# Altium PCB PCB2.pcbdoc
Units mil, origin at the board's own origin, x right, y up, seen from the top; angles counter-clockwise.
Board outline 3201.08 x 2165 mil, 2 copper layers (Top Layer, Bottom Layer); 34 components, 17 nets, 90 pads, 14 vias.
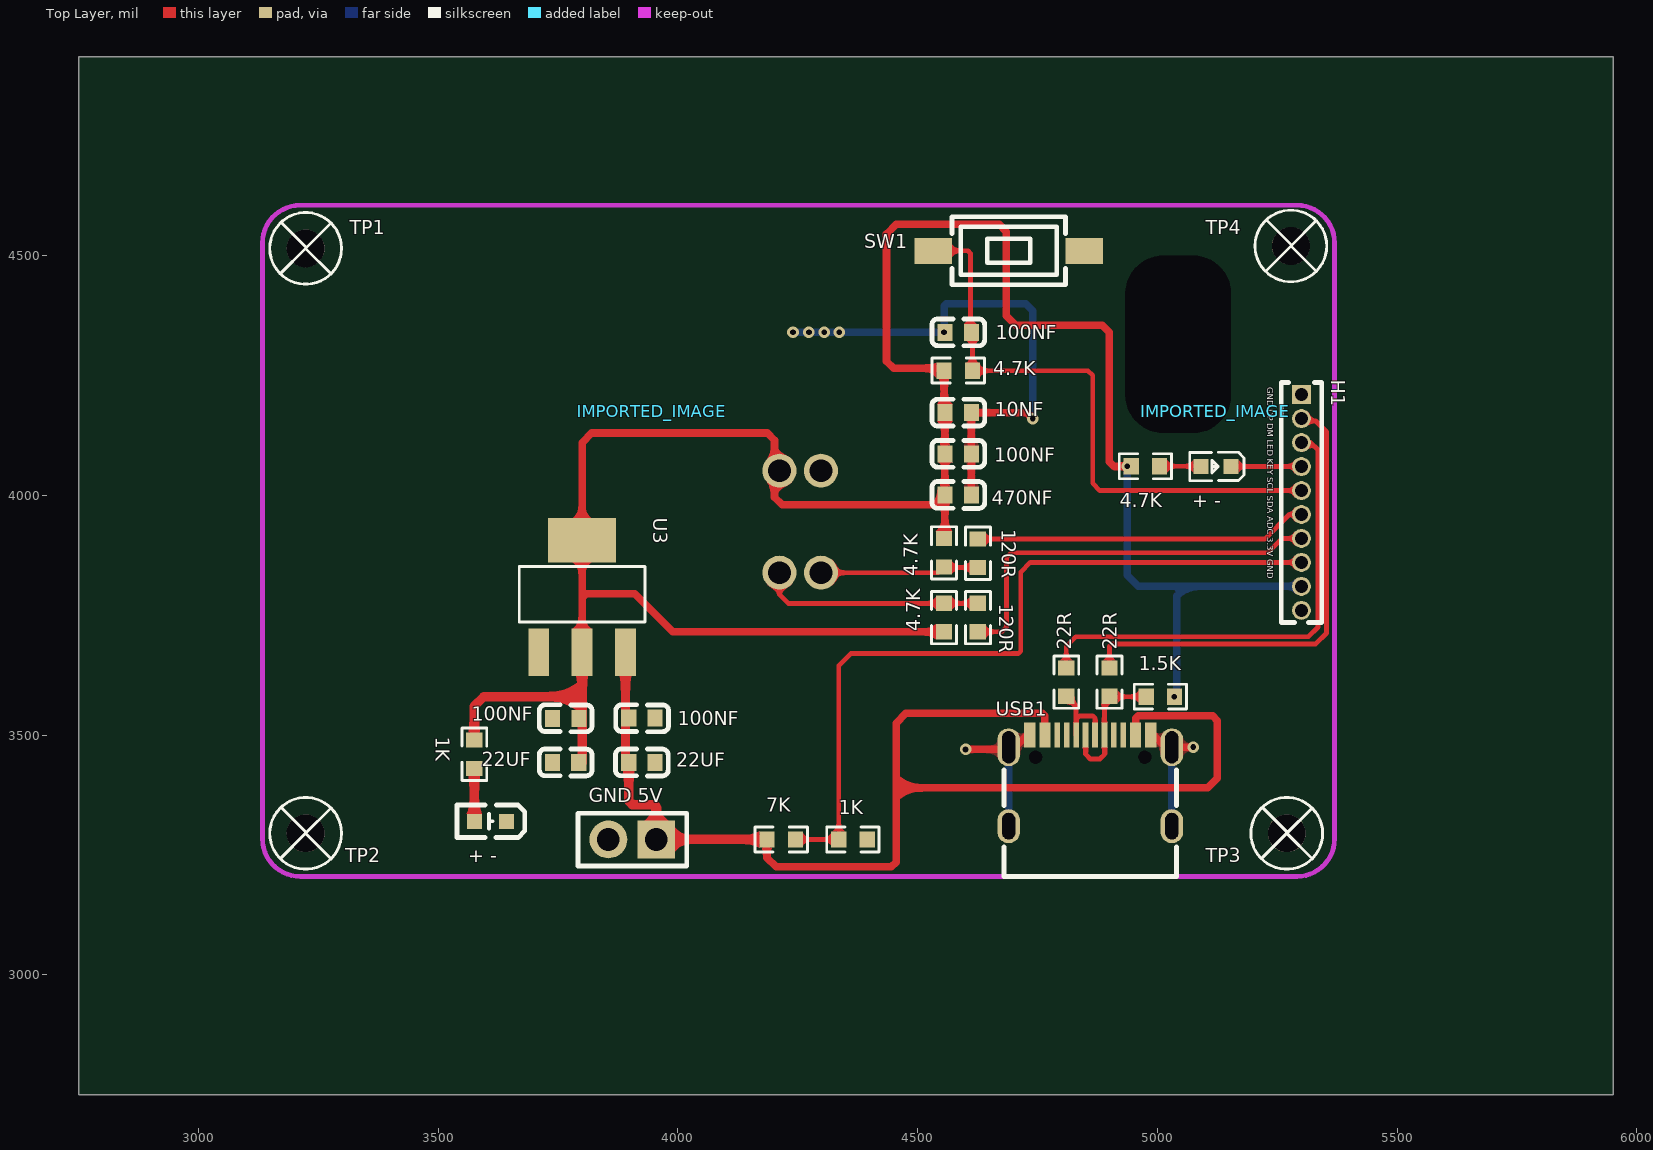
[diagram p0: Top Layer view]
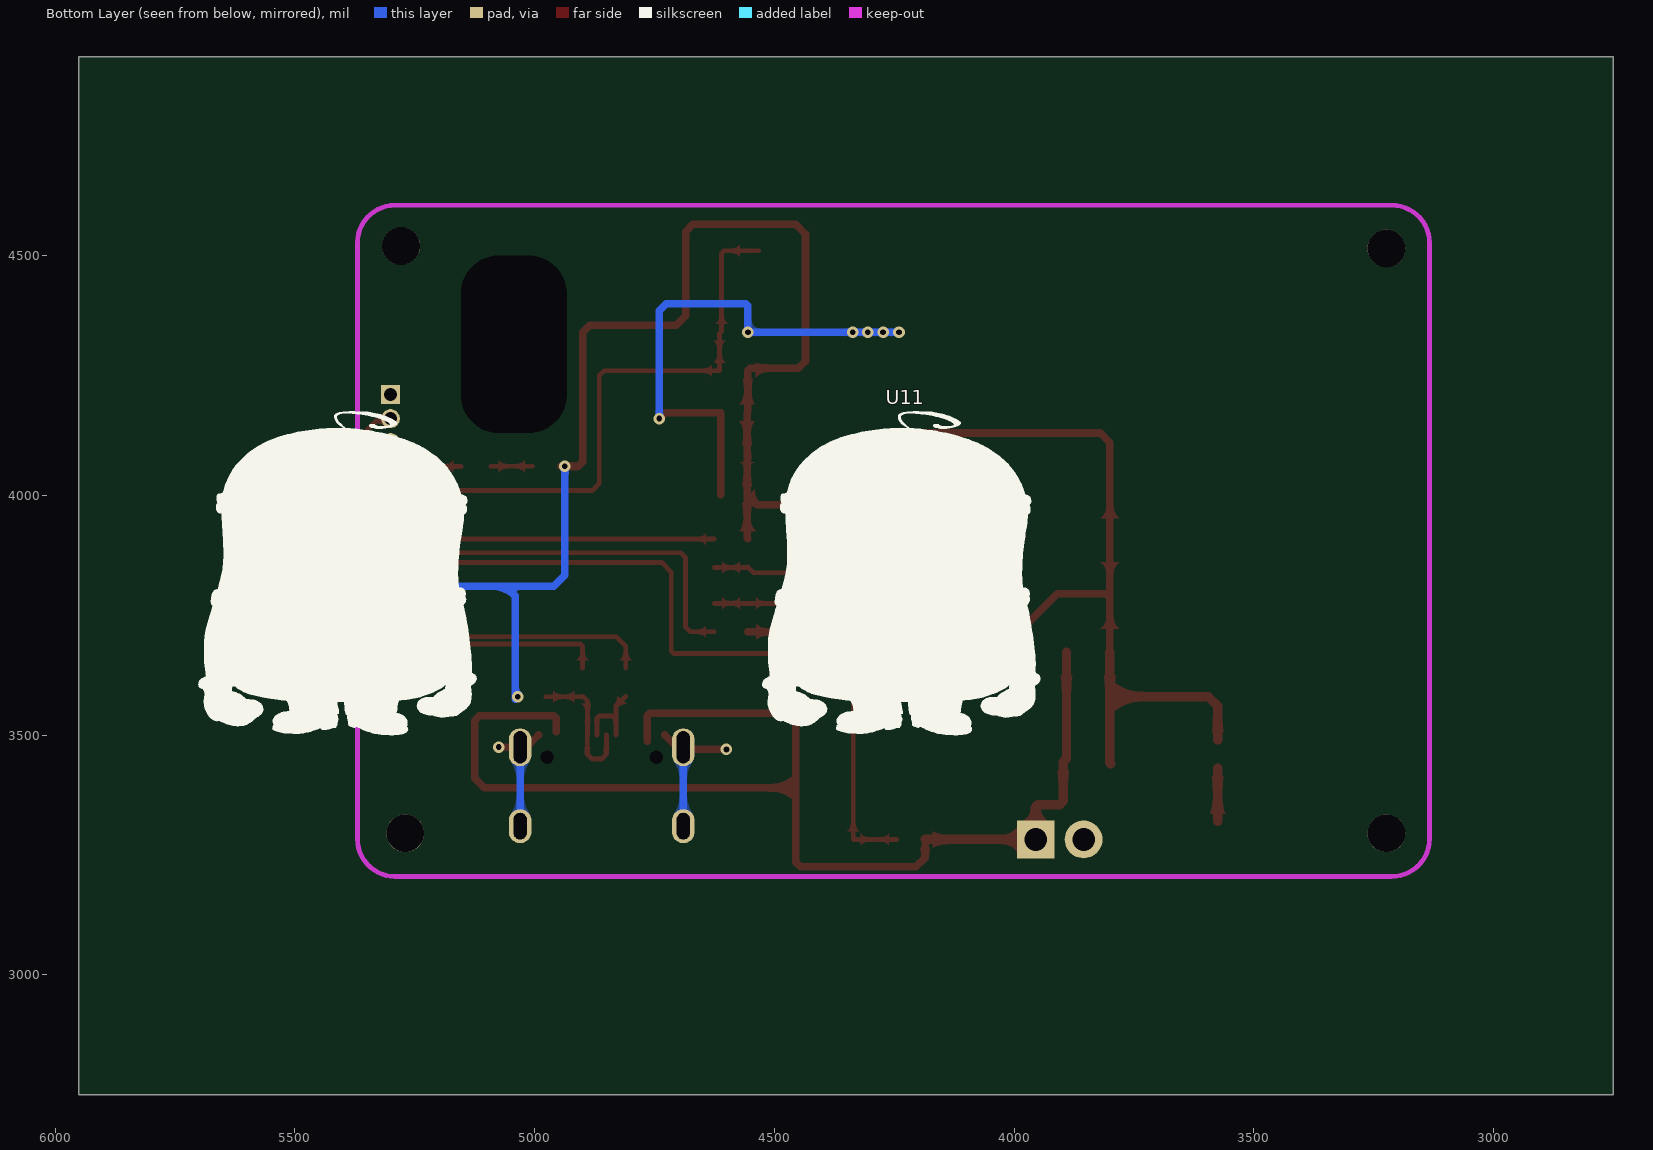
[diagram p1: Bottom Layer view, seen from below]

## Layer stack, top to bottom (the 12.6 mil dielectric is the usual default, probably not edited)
Top Layer: signal copper (thickness not stored)
Dielectric: dielectric 12.6, FR-4, Dk 4.8
Bottom Layer: signal copper (thickness not stored)

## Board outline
5951.08,2750 2750,2750 2750,4915 5951.08,4915
cut-out: 5012.18,4500 5074.7,4500 cw(c5074.7,4421.26) 5153.44,4421.26 5153.44,4208.74 cw(c5074.7,4208.74) 5074.7,4130 5012.18,4130 cw(c5012.18,4208.74) 4933.44,4208.74 4933.44,4421.26 cw(c5012.18,4421.26)

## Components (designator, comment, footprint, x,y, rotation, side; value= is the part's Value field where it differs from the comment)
1.5K "Res_0603" R0603 5006.28,3580 r180 top
1K "ERJ3GEYJ102V" R0603 3575.25,3460 r270 top
1K "Res_0603" R0603 4365,3282.24 r180 top
4.7K "Res_0603" R0603 4555,3745 r90 top
4.7K "Res_0603" R0603 4555,3880 r270 top
4.7K "Res_0603" R0603 4584.66,4260 r0 top
4.7K "Res_0603" R0603 4975,4060.56 r0 top
7K "Res_0603" R0603 4215.34,3282.24 r180 top
10NF "CAP_0603" C0603 4584.53,4172.47 r180 top
22R "Res_0603" R0603 4900,3610.34 r90 top
22R "Res_0603" R0603 4810,3610.34 r90 top
22UF "GRM186R60J226ME15D" C0603 3925,3442.73 r0 top
22UF "GRM186R60J226ME15D" C0603 3765.61,3442.94 r180 top
100NF "CAP_0603" C0603 4584.53,4086.66 r180 top
100NF "CAP_0603" C0603 4584.53,4340 r180 top
100NF "HMK107B7104KA-T" C0603 3925,3535.21 r180 top
100NF "HMK107B7104KA-T" C0603 3766.22,3535 r0 top
120R "Res_0603" R0603 4625.54,3745 r270 top
120R "Res_0603" R0603 4625.54,3879.1 r270 top
470NF "CAP_0603" C0603 4584.53,4000.86 r180 top
"+ -" "LED_0603-R" LED_0603 5120.26,4060 r180 top
"+ -" "SZYY0603B" LED0603-R-RD_BLUE 3609,3320 r180 top
"GND 5V" "HDR-F_2.54_1x2P" HDR-TH_2P-P2.54-V-F 3905,3282.24 r180 top
H1 "KH-1.27PH180-1X10P-L7.2" HDR-TH_10P-P1.27-V-M 5300.5,3985 r270 top
IMPORTED_IMAGE "IMPORTED_IMAGE" IMPORTED_IMAGE 3945,4175.01 r0 top
IMPORTED_IMAGE "IMPORTED_IMAGE" IMPORTED_IMAGE 5121.08,4175.01 r0 top
SW1 "TSA363G25-250B" SW-SMD_L6.1-W3.6-LS8.0 4690,4510 r0 top
TP1 "M2螺丝" M2螺丝 3223.44,4515 r0 top
TP2 "M2螺丝" M2螺丝 3223.44,3295 r0 top
TP3 "M2螺丝" M2螺丝 5269.83,3295 r0 top
TP4 "M2螺丝" M2螺丝 5278.44,4520 r0 top
U3 "AMS1117-3.3_1" SOT-223-3_L6.4-W3.5-P2.30-LS7.0-BR 3800,3789.52 r270 top
U11 "MLX90640ESF-BAB-000-TU" TO-39-4_MELEXIS_MLX90640 4255,3945 r0 bottom
USB1 "kh-type-c-16p" usb-c-smd_kh-type-c-16p 4860,3405 r0 top

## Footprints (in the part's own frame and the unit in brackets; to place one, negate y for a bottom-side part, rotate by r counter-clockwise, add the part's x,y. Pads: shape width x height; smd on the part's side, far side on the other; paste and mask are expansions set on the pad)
C0603 [mm]
  rect 0.8x0.9 smd paste+0 mask+0.051: 1(-0.7,0) 2(0.7,0)
  silkscreen extent -1.41,-0.71 1.39,0.72
HDR-TH_2P-P2.54-V-F [mm]
  rect 2x2 hole 1.2 paste+0 mask+0.051: 1(-1.27,0)
  round 2 hole 1.2 paste+0 mask+0.051: 2(1.27,0)
  silkscreen extent -2.88,-1.39 2.88,1.4
HDR-TH_10P-P1.27-V-M [mm]
  rect 1x1 hole 0.7 mask+0.051: 1(-5.715,0)
  round 1 hole 0.7 mask+0.051: 2(-4.445,0) 3(-3.175,0) 4(-1.905,0) 5(-0.635,0) 6(0.635,0) 7(1.905,0) 8(3.175,0) 9(4.445,0) 10(5.715,0)
  silkscreen extent -6.35,-1.07 6.35,1.07
IMPORTED_IMAGE [mil]
LED0603-R-RD_BLUE [mil]
  rect 31.5x31.5 smd paste+0 mask+2: 1(33.5,0) 2(-33.5,0)
  silkscreen extent -72,-34 70,34
LED_0603 [mil]
  rect 31.5x31.5 smd paste+0 mask+2: 1(-33.5,-0.4) 2(29.5,-0.2)
  silkscreen extent -61,-30 53,30
M2螺丝 [mm]
  round 2 hole 2 mask+0.051: 1(0,0)
  silkscreen extent -1.9,-1.9 1.9,1.9
R0603 [mil]
  rect 31.75x34.02 smd paste-3937.01 mask+2: 1(-29.66,0) 2(29.66,0)
  silkscreen extent -55,-26 55,26
SOT-223-3_L6.4-W3.5-P2.30-LS7.0-BR [mil]
  rect 98.4x43.3 smd paste+0 mask+2: 1(116.9,-90.5) 2(116.9,0) 3(116.9,90.6)
  rect 92.1x141.7 smd paste+0 mask+2: 4(-116.9,0)
  silkscreen extent -62,-131 54,131
SW-SMD_L6.1-W3.6-LS8.0 [mm]
  rect 2x1.38 smd mask+0.051: 1(-4,0) 2(4,0)
  silkscreen extent -3,-1.8 3,1.8
TO-39-4_MELEXIS_MLX90640 [mm]
  round 1.8 hole 1.2 copper offset 0,-0.001 paste+0 mask+0.05: 1(-1.1,2.699) 2(-1.1,-2.701) 3(1.101,-2.701) 4(1.101,2.699)
  silkscreen extent -4.6,-4.6 4.6,5.3
usb-c-smd_kh-type-c-16p [mm]
  oval 1.2x2 hole 0.7 slot 1.7 at 90 deg paste+0 mask+0.051: 1(-4.32,1.765) 2(4.32,1.765)
  oval 1.2x1.8 hole 0.7 slot 1.4 at 90 deg paste+0 mask+0.051: 3(-4.32,-2.415) 4(4.32,-2.415)
  rect 0.3x1.3 smd paste-100 mask+0.051: A1(-3.35,2.415) A4(-2.55,2.415) A5(-1.25,2.415) A6(-0.25,2.415) A7(0.25,2.415) A8(1.25,2.415) A9(2.55,2.415) A12(3.35,2.415) B1(3.05,2.415) B4(2.25,2.415) B5(1.75,2.415) B6(0.75,2.415) B7(-0.75,2.415) B8(-1.75,2.415) B9(-2.25,2.415) B12(-3.05,2.415)
  Multi-Layer board cut-out: -2.54,1.235 -2.575,1.387 -2.672,1.509 -2.812,1.576 -2.968,1.576 -3.108,1.509 -3.205,1.387 -3.24,1.235 -3.24,1.235 -3.205,1.083 -3.108,0.961 -2.968,0.894 -2.812,0.894 -2.672,0.961 -2.575,1.083 -2.54,1.235
  Multi-Layer board cut-out: 3.24,1.235 3.205,1.387 3.108,1.509 2.968,1.576 2.812,1.576 2.672,1.509 2.575,1.387 2.54,1.235 2.54,1.235 2.575,1.083 2.672,0.961 2.812,0.894 2.968,0.894 3.108,0.961 3.205,1.083 3.24,1.235
  silkscreen extent -4.57,-5.08 4.57,0.57

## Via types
v1: diameter 24.02, hole 12.01, Top Layer to Bottom Layer, 14 vias

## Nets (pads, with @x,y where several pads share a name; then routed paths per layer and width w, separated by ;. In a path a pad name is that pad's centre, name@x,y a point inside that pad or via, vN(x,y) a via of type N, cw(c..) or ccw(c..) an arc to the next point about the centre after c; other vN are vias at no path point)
$1N282: 4.7K.2@4555,3774.66 120R.1@4625.54,3774.66 U11.1 | length 467
  Top Layer w10: U11.1 4211.69,3793.31 4230.34,3774.66 4555,3774.66 120R.1@4625.54,3774.66
$1N283: 4.7K.2@4555,3850.34 120R.2@4625.54,3849.44 U11.4 | length 332.4
  Top Layer w10: U11.4 4543.36,3838.7 4555,3850.34 4555.9,3849.44 120R.2@4625.54,3849.44
$1N1069: 4.7K.2@5004.66,4060.56 "+ -.2"@5090.76,4060.2 | length 86.3
  Top Layer w10: 4.7K.2@5004.66,4060.56 5090.41,4060.56 5090.76,4060.2
$1N1386: 1K.2@3575.25,3430.34 "+ -.1"@3575.5,3320 | length 110.4
  Top Layer w19.68: 1K.2@3575.25,3430.34 3575.25,3320.25 3575.5,3320
+3.3V: 1.5K.1 1K.1@3575.25,3489.66 4.7K.1 10NF.2 22UF.1@3793.17,3442.94 100NF.2@3793.78,3535 100NF.2@4556.97,4086.66 470NF.2 H1.9 U3.2 U3.4 U11.2 | length 5276.9
  Top Layer w15.75: U3.2 3800,3786.63 ; 4.7K.1@4555,3715.34 3989.66,3715.34 3910,3795 3808.37,3795 3800,3786.63 ; 4.7K.1@4555,3909.66 4556.97,3911.63 470NF.2 ; 4.7K.1@4945.34,4060.56 4909.44,4060.56 4900,4070 4900,4340 4885,4355 4705,4355 4685,4375 4685,4550 4670,4565 4455,4565 4435,4545 4435,4280 4450,4265 4550,4265 4555,4260 4555,4174.44 10NF.2 100NF.2@4556.97,4086.66 ; 3800,3786.63 U3.4 3800,4110 3820,4130 4186.42,4130 4201.42,4115 4201.42,3995.75 4217.16,3980 4536.11,3980 470NF.2 ; 470NF.2 4556.97,4060 ; 4556.97,4060 4555,4084.7 100NF.2@4556.97,4086.66 ; 4556.97,4060 100NF.2@4556.97,4086.66
  Top Layer w19.68: 1K.1@3575.25,3489.66 3575.25,3560.25 3595,3580 3799.29,3580 3800,3580.71 ; 22UF.1@3798.17,3440 3800,3441.83 3800,3580.71 ; U3.2 3800,3580.71
  Bottom Layer w15.75: v1(4936.91,4060.56) 4936.91,3833.09 4960,3810 5060,3810 ; v1@5040,3575 5040,3790 5060,3810 ; v1(5300.5,3810) 5060,3810
  other v1: 5035.22,3579.72
+5V: 7K.2 22UF.1@3897.44,3442.73 100NF.2@3897.44,3535.21 "GND 5V.1" U3.3 USB1.A4 USB1.A9 USB1.B4 USB1.B9 | length 2652.1
  Top Layer w15.75: 7K.2 4185.68,3244.32 4205,3225 4445,3225 4455,3235 4455,3392.84 ; USB1.A4@4765,3486.9 4765,3540 4760,3545 4475,3545 4455,3525 4455,3392.84 ; USB1.A9@4955,3506.49 4955,3535 4960,3540 5115,3540 5125,3530 5125,3410 5105,3390 4457.85,3390 4455,3392.84
  Top Layer w19.68: U3.3 3890.6,3450.89 22UF.1@3897.44,3444.05 ; 22UF.1@3897.44,3435 3897.44,3362.56 3905,3355 3950,3355 3955,3350 3955,3282.24 7K.2
BAT_ADC: 1K.2@4335.34,3282.24 7K.1 H1.8 | length 1603.9
  Top Layer w10: 7K.1 4335.34,3282.24 4335.34,3644.88 4360.46,3670 4710,3670 4715,3675 4715,3840 4735,3860 H1.8
GND: 1K.1@4394.66,3282.24 10NF.1 22UF.2 100NF.1@3738.66,3535 100NF.1@3952.56,3535.21 100NF.1@4612.09,4086.66 100NF.2@4556.97,4340 470NF.1 "+ -.2"@3642.5,3320 "GND 5V.2" H1.1 H1.10 SW1.2 U3.1 U11.3 USB1.1 USB1.2 USB1.3 USB1.4 USB1.A1 USB1.A12 USB1.B1 USB1.B12 | length 1656.6
  Top Layer w15.75: v1(4600,3470) 4685.43,3470 USB1.1 4702.52,3474.49 USB1.A1 ; 470NF.1 4612.09,4086.66 10NF.1 4727.53,4172.47 v1(4740,4160) ; USB1.A12 5017.48,3474.49 v1(5030.08,3474.49) 5074.49,3474.49 v1(5075,3475)
  Bottom Layer w15.75: v1(4240,4340) v1(4273.18,4340) v1(4305.35,4340) v1(4336.44,4340) v1(4555,4340) 4555,4395 4560,4400 4725,4400 4740,4385 v1(4740,4160) ; USB1.3 USB1.1 ; USB1.4 v1(5030.08,3474.49)
  other v1: 4740,4160 4740,4160
IIC_SCL: 120R.1@4625.54,3908.76 H1.6 | length 696.2
  Top Layer w10: 120R.1@4625.54,3908.76 5223.76,3908.76 5275,3960 H1.6
IIC_SDA: 120R.2@4625.54,3715.34 H1.7 | length 840.5
  Top Layer w10: 120R.2@4625.54,3715.34 4675.34,3715.34 4685,3725 4685,3870 4695,3880 5230,3880 5260,3910 H1.7
KEY_GPIO: 4.7K.2@4614.32,4260 100NF.1@4612.09,4340 H1.5 SW1.1 | length 1247.9
  Top Layer w10: SW1.1 4605,4510 4610,4505 4610,4342.09 4612.09,4340 4614.32,4337.77 4614.32,4260 4855,4260 4865,4250 4865,4025 4880,4010 H1.5
LED_GPIO: "+ -.1"@5153.76,4060.4 H1.4 | length 146.9
  Top Layer w10: 5153.76,4060.4 5300.1,4060.4 H1.4
USB-D+: 1.5K.2 22R.1@4900,3580.68 USB1.A6 USB1.B6 | length 290.4
  Top Layer w10: USB1.A6 4850.16,3459.84 4860,3450 4880,3450 4890,3460 4890,3499.61 USB1.B6 4889.53,3570.21 4900,3580.68 4900.68,3580 1.5K.2
USB-D-: 22R.1@4810,3580.68 USB1.A7 USB1.B7 | length 168.7
  Top Layer w10: 22R.1@4810,3580.68 4830.47,3560.21 4830.47,3532.59 ; USB1.B7 4830.47,3532.59 ; USB1.A7 4870,3500.24 4870,3535 4865,3540 4837.88,3540 4830.47,3532.59
USB_FS_DM: 22R.2@4810,3640 H1.3 | length 997.3
  Top Layer w10: 22R.2@4810,3640 4810,3685 4830,3705 5315,3705 5335,3725 5335,4095 5320,4110 H1.3
USB_FS_DP: 22R.2@4900,3640 H1.2 | length 992.6
  Top Layer w10: 22R.2@4900,3640 4900,3685 4905,3690 5330,3690 5352.86,3712.86 5352.86,4132.14 5330,4155 5305.5,4155 H1.2
"": TP1.1 TP2.1 TP3.1 TP4.1 USB1.A5 USB1.A8 USB1.B5 USB1.B8

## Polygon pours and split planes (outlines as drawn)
GND on Bottom Layer (hatched 45Degree grid 30 track 10, remove dead copper, pour order 0): 3000,3100 5415,3100 5415,4665 3000,4665
GND on Top Layer (hatched 45Degree grid 30 track 10, remove dead copper, pour order 1): 3105,3000 5540,3000 5540,4660 3105,4660

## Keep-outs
Board Outline Layer:
  lines w10 net "": 3133.44,3283.74 ccw(c3212.18,3283.74) 3212.18,3205 5290.92,3205 ccw(c5290.92,3283.74) 5369.66,3283.74 5369.66,4526.26 ccw(c5290.92,4526.26) 5290.92,4605 3212.18,4605 ccw(c3212.18,4526.26) 3133.44,4526.26 3133.44,3283.74

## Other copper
Top Layer:
  region net +3.3V: 4209.29,4099.54 4193.54,4099.54 4193.45,4097.3 4193.2,4094.91 4192.78,4092.41 4192.21,4089.85 4191.49,4087.28 4190.64,4084.74 4189.66,4082.28 4188.56,4079.95 4187.77,4078.5 4186.93,4077.13 4186.04,4075.88 4185.12,4074.74 4238.27,4074.74 4237.55,4075.5 4236.75,4076.25 4235.42,4077.35 4233.43,4078.79 4230.11,4080.89 4220.47,4086.47 4217.62,4088.3 4215.52,4089.81 4214.09,4090.99 4213.21,4091.79 4212.4,4092.62 4211.68,4093.46 4211.03,4094.33 4210.48,4095.21 4210.02,4096.13 4209.83,4096.6 4209.67,4097.07 4209.54,4097.55 4209.43,4098.04 4209.35,4098.53 4209.31,4099.03
  region net +3.3V: 4193.54,4003.06 4209.29,4003.06 4209.31,4003.57 4209.35,4004.07 4209.43,4004.57 4209.54,4005.06 4209.67,4005.54 4209.83,4006.01 4210.02,4006.48 4210.48,4007.39 4211.03,4008.28 4211.68,4009.14 4212.4,4009.99 4213.21,4010.81 4214.55,4012.01 4216.03,4013.18 4218.17,4014.68 4222.26,4017.2 4231.25,4022.41 4233.95,4024.17 4235.42,4025.25 4236.75,4026.35 4237.55,4027.1 4238.27,4027.87 4185.12,4027.87 4186.04,4026.73 4186.93,4025.47 4187.77,4024.11 4188.94,4021.89 4190,4019.51 4190.94,4017.03 4191.74,4014.47 4192.41,4011.9 4192.93,4009.35 4193.3,4006.88 4193.5,4004.53
  region net $1N283: 4346.55,3833.7 4346.55,3843.7 4344.39,3843.77 4343.08,3843.89 4341.87,3844.07 4340.76,3844.31 4339.74,3844.6 4338.79,3844.95 4337.92,3845.34 4337.12,3845.78 4336.38,3846.27 4335.7,3846.81 4335.06,3847.38 4334.47,3848 4333.91,3848.65 4333.12,3849.7 4332.13,3851.22 4329.36,3855.95 4327.86,3858.31 4326.45,3860.26 4325.24,3861.75 4323.86,3863.26 4322.31,3864.77 4321.75,3865.28 4321.75,3812.13 4323.37,3813.64 4324.8,3815.15 4326.06,3816.65 4327.53,3818.61 4329.08,3820.99 4331.89,3825.79 4332.87,3827.34 4333.64,3828.41 4334.18,3829.08 4334.76,3829.72 4335.38,3830.32 4336.04,3830.87 4336.75,3831.38 4337.52,3831.85 4338.35,3832.27 4339.25,3832.64 4340.24,3832.95 4341.3,3833.22 4342.46,3833.43 4343.72,3833.58 4345.8,3833.69
  region net $1N282: 4206.69,3793.31 4216.69,3793.31 4216.74,3794.07 4216.87,3794.83 4217.1,3795.59 4217.4,3796.34 4217.77,3797.09 4218.22,3797.84 4218.73,3798.58 4219.93,3800.05 4221.33,3801.51 4223.72,3803.65 4228.16,3807.11 4235.05,3812.29 4236.49,3813.5 4237.73,3814.69 4238.27,3815.27 4185.12,3815.27 4186.25,3814.1 4187.59,3812.9 4190.76,3810.4 4198.8,3804.35 4201.29,3802.23 4202.77,3800.78 4204.08,3799.32 4204.65,3798.58 4205.16,3797.84 4205.61,3797.09 4205.99,3796.34 4206.29,3795.59 4206.51,3794.83 4206.64,3794.07
  region net IIC_SDA: 4657.55,3710.34 4657.55,3720.34 cw(c4657.55,3739.09) 4642.55,3727.84 4642.55,3702.84 cw(c4657.55,3691.59)
  region net $1N282: 4593.53,3779.66 4593.53,3769.66 cw(c4593.53,3750.91) 4608.53,3762.16 4608.53,3787.16 cw(c4593.53,3798.41)
  region net $1N283: 4593.53,3854.44 4593.53,3844.44 cw(c4593.53,3825.69) 4608.53,3836.94 4608.53,3861.94 cw(c4593.53,3873.19)
  region net IIC_SCL: 4657.55,3903.76 4657.55,3913.76 cw(c4657.55,3932.51) 4642.55,3921.26 4642.55,3896.26 cw(c4657.55,3885.01)
  region net $1N282: 4522.99,3779.66 4522.99,3769.66 cw(c4522.99,3750.91) 4537.99,3762.16 4537.99,3787.16 cw(c4522.99,3798.41)
  region net $1N282: 4587.01,3769.66 4587.01,3779.66 cw(c4587.01,3798.41) 4572.01,3787.16 4572.01,3762.16 cw(c4587.01,3750.91)
  region net +3.3V: 4514.37,3723.21 4514.37,3707.47 cw(c4514.37,3668.6) 4537.99,3699.46 4537.99,3731.22 cw(c4514.37,3762.08)
  region net $1N283: 4587.01,3844.44 4587.01,3854.44 cw(c4587.01,3873.19) 4572.01,3861.94 4572.01,3836.94 cw(c4587.01,3825.69)
  region net +3.3V: 4564.84,3949.16 4549.09,3949.16 cw(c4518.41,3949.16) 4537.99,3925.54 4572.01,3925.54 cw(c4607.35,3949.16)
  region net +3.3V: 4530.54,3985.57 4541.68,3974.43 cw(c4563.28,3952.83) 4567.09,3983.14 4541.22,4012.95 cw(c4504.69,4011.42)
  region net +3.3V: 4549.09,3959.52 4564.84,3959.52 cw(c4733.65,3959.52) 4566.5,3983.14 4547.43,3983.14 cw(c4380.28,3959.52)
  region net +3.3V: 4564.84,4042.2 4549.09,4042.2 cw(c4380.28,4042.2) 4547.43,4018.57 4566.5,4018.57 cw(c4733.65,4042.2)
  region net +3.3V: 4549.09,4060 4564.84,4060 cw(c4573.86,4060) 4572.71,4068.95 4541.22,4068.95 cw(c4540.07,4060)
  region net +3.3V: 4564.84,4128 4549.09,4128 cw(c4380.28,4128) 4547.43,4104.38 4566.5,4104.38 cw(c4733.65,4128)
  region net +3.3V: 4562.87,4213.81 4547.13,4213.81 cw(c4496.94,4213.81) 4541.22,4190.19 4572.71,4190.19 cw(c4596.15,4213.81)
  region net +3.3V: 4549.09,4131.13 4564.84,4131.13 cw(c4604.21,4131.13) 4572.71,4154.75 4541.22,4154.75 cw(c4509.72,4131.13)
  region net USB-D-: 4835.47,3532.59 4825.47,3532.59 cw(c4797.15,3532.59) 4824.61,3525.67 4836.33,3525.67 cw(c4863.79,3532.59)
  region net USB-D+: 4845.16,3459.84 4855.16,3459.84 cw(c4980.45,3459.84) 4856.02,3474.49 4844.3,3474.49 cw(c4719.87,3459.84)
  region net USB-D-: 4875,3535 4865,3535 cw(c4823.62,3535) 4863.93,3525.67 4875.75,3525.67 cw(c4933.75,3535)
  region net USB-D+: 4885,3460 4895,3460 cw(c5136.25,3460) 4895.44,3474.49 4883.62,3474.49 cw(c4808,3460)
  region net USB-D+: 4894.53,3540.67 4884.53,3540.67 cw(c4753.19,3540.67) 4883.67,3525.67 4895.39,3525.67 cw(c5025.87,3540.67)
  region net USB_FS_DP: 4905,3670.88 4895,3670.88 cw(c4876.25,3670.88) 4887.5,3655.88 4912.5,3655.88 cw(c4923.75,3670.88)
  region net USB-D+: 4884.53,3549.8 4894.53,3549.8 cw(c4913.28,3549.8) 4902.03,3564.8 4882.99,3564.8 cw(c4810.61,3549.8)
  region net USB-D+: 4932.01,3575 4932.01,3585 cw(c4932.01,3603.75) 4917.01,3592.5 4917.01,3567.5 cw(c4932.01,3556.25)
  region net USB_FS_DM: 4815,3670.88 4805,3670.88 cw(c4786.25,3670.88) 4797.5,3655.88 4822.5,3655.88 cw(c4833.75,3670.88)
  region net USB-D-: 4826.93,3556.67 4834.01,3563.75 cw(c4850.92,3580.66) 4827.01,3581.35 4808.2,3564.8 cw(c4807.27,3537.01)
  region net USB-D+: 4945.75,3585 4945.75,3575 cw(c4945.75,3556.25) 4960.75,3567.5 4960.75,3592.5 cw(c4945.75,3603.75)
  region net KEY_GPIO: 4586.89,4505 4586.89,4515 cw(c4586.89,4533.75) 4571.89,4522.5 4571.89,4497.5 cw(c4586.89,4486.25)
  region net KEY_GPIO: 4615,4372.72 4605,4372.72 cw(c4586.25,4372.72) 4597.5,4357.72 4622.5,4357.72 cw(c4633.75,4372.72)
  region net KEY_GPIO: 4609.32,4307.28 4619.32,4307.28 cw(c4638.07,4307.28) 4626.82,4322.28 4601.82,4322.28 cw(c4590.57,4307.28)
  region net KEY_GPIO: 4645.2,4255 4645.2,4265 cw(c4645.2,4283.75) 4630.2,4272.5 4630.2,4247.5 cw(c4645.2,4236.25)
  region net KEY_GPIO: 4619.32,4292.01 4609.32,4292.01 cw(c4590.57,4292.01) 4601.82,4277.01 4626.82,4277.01 cw(c4638.07,4292.01)
  region net +3.3V: 4547.13,4219.37 4562.87,4219.37 cw(c4731.68,4219.37) 4564.53,4242.99 4545.47,4242.99 cw(c4378.32,4219.37)
  region net +3.3V: 4515.5,4272.87 4515.5,4257.13 cw(c4515.5,4227.6) 4539.12,4245.31 4539.12,4277.01 cw(c4515.5,4342.43)
  region net $1N1069: 5035.54,4055.56 5035.54,4065.56 cw(c5035.54,4084.31) 5020.54,4073.06 5020.54,4048.06 cw(c5035.54,4036.81)
  region net +3.3V: 4909.44,4068.43 4909.44,4052.68 cw(c4909.44,3931.19) 4929.46,4051.02 4929.46,4070.09 cw(c4909.44,4189.92)
  region net LED_GPIO: 5184.51,4055.4 5184.51,4065.4 cw(c5184.51,4084.15) 5169.51,4072.9 5169.51,4047.9 cw(c5184.51,4036.65)
  region net $1N1069: 5060.01,4065.56 5060.01,4055.56 cw(c5060.01,4036.81) 5075.01,4048.06 5075.01,4073.06 cw(c5060.01,4084.31)
  region net +3.3V: 3792.13,3836.75 3807.87,3836.75 cw(c3837.4,3836.75) 3819.68,3860.37 3780.32,3860.37 cw(c3762.6,3836.75)
  region net +3.3V: 3807.87,3976.09 3792.13,3976.09 cw(c3762.6,3976.09) 3780.32,3952.47 3819.68,3952.47 cw(c3837.4,3976.09)
  region net +5V: 3880.76,3593.89 3900.44,3593.89 cw(c4111.45,3593.89) 3902.52,3623.42 3878.68,3623.42 cw(c3669.75,3593.89)
  region net +3.3V: 3807.87,3745.44 3792.13,3745.44 cw(c3762.6,3745.44) 3780.32,3721.82 3819.68,3721.82 cw(c3837.4,3745.44)
  region net +3.3V: 3790.16,3593.89 3809.84,3593.89 cw(c4020.85,3593.89) 3811.92,3623.42 3788.08,3623.42 cw(c3579.15,3593.89)
  region net $1N1386: 3585.09,3365.28 3565.41,3365.28 cw(c3485.52,3365.28) 3559.75,3335.75 3591.25,3335.75 cw(c3658.97,3365.28)
  region net $1N1386: 3565.41,3384.94 3585.09,3384.94 cw(c3796.1,3384.94) 3587.17,3414.46 3563.33,3414.46 cw(c3354.4,3384.94)
  region net +3.3V: 3585.09,3535.06 3565.41,3535.06 cw(c3354.4,3535.06) 3563.33,3505.54 3587.17,3505.54 cw(c3796.1,3535.06)
  region net +5V: 3887.6,3395.48 3907.28,3395.48 cw(c4118.29,3395.48) 3909.36,3425.01 3885.52,3425.01 cw(c3676.59,3395.48)
  region net +5V: 3964.84,3350 3945.16,3350 cw(c3910.48,3350) 3930.39,3321.61 3979.61,3321.61 cw(c3999.52,3350)
  region net +5V: 4023.9,3272.4 4023.9,3292.08 cw(c4023.9,3328.99) 3994.37,3306.85 3994.37,3257.64 cw(c4023.9,3235.49)
  region net BAT_ADC: 4340.34,3314.25 4330.34,3314.25 cw(c4311.59,3314.25) 4322.84,3299.25 4347.84,3299.25 cw(c4359.09,3314.25)
  region net BAT_ADC: 4304.46,3287.24 4304.46,3277.24 cw(c4304.46,3258.49) 4319.46,3269.74 4319.46,3294.74 cw(c4304.46,3305.99)
  region net +5V: 4177.81,3244.32 4193.55,3244.32 cw(c4326.06,3244.32) 4195.21,3265.23 4176.15,3265.23 cw(c4045.3,3244.32)
  region net +5V: 4140.28,3292.08 4140.28,3272.4 cw(c4140.28,3207.98) 4169.8,3265.23 4169.8,3299.25 cw(c4140.28,3356.51)
  region net BAT_ADC: 4275.88,3277.24 4275.88,3287.24 cw(c4275.88,3305.99) 4260.88,3294.74 4260.88,3269.74 cw(c4275.88,3258.49)
  region net BAT_ADC: 5273.7,3865 5273.7,3855 5275.01,3854.94 5275.62,3854.88 5276.19,3854.78 5276.73,3854.66 5277.24,3854.52 5277.73,3854.35 5278.19,3854.16 5278.63,3853.95 5279.05,3853.72 5279.46,3853.47 5280.22,3852.91 5280.94,3852.28 5281.62,3851.6 5283.67,3849.25 5285.6,3847.06 5286.98,3845.69 5287.48,3845.24 5287.48,3874.76 5286.04,3873.39 5284.4,3871.61 5281.96,3868.77 5281.28,3868.05 5280.58,3867.39 5279.85,3866.8 5279.46,3866.53 5279.05,3866.28 5278.63,3866.05 5278.19,3865.84 5277.73,3865.65 5277.24,3865.48 5276.73,3865.34 5276.19,3865.22 5275.62,3865.12 5274.38,3865.01
  region net LED_GPIO: 5273.7,4065.4 5273.7,4055.4 5275.06,4055.34 5275.68,4055.27 5276.26,4055.17 5276.81,4055.05 5277.33,4054.9 5277.82,4054.72 5278.29,4054.53 5278.73,4054.31 5279.14,4054.07 5279.54,4053.8 5279.92,4053.52 5280.64,4052.91 5281.31,4052.22 5282.29,4051.09 5284.73,4048.06 5285.99,4046.66 5286.96,4045.71 5287.48,4045.24 5287.48,4074.76 5286.08,4073.45 5283.36,4070.52 5281.96,4069.01 5281.26,4068.33 5280.53,4067.7 5279.77,4067.13 5278.97,4066.63 5278.54,4066.41 5278.1,4066.2 5277.63,4066.02 5277.15,4065.86 5276.64,4065.73 5276.11,4065.61 5274.97,4065.45
  region net USB_FS_DP: 5327.3,4150 5327.3,4160 5326.78,4160.03 5326.27,4160.13 5325.77,4160.28 5325.28,4160.48 5324.79,4160.74 5324.32,4161.05 5323.85,4161.4 5323.38,4161.79 5322.48,4162.68 5321.59,4163.7 5320.31,4165.4 5316.66,4170.9 5315.48,4172.56 5314.7,4173.55 5313.91,4174.4 5313.52,4174.76 5313.52,4145.24 5314.15,4145.75 5314.85,4146.24 5315.6,4146.7 5317.27,4147.57 5319.08,4148.32 5320.97,4148.96 5322.88,4149.45 5324.74,4149.8 5326.49,4149.98
  region net USB_FS_DM: 5325.67,4097.26 5332.74,4104.33 5332.06,4104.9 5331.28,4105.37 5330.4,4105.78 5329.44,4106.14 5325.33,4107.28 5323.4,4107.89 5322.54,4108.26 5321.78,4108.68 5321.14,4109.17 5320.64,4109.76 5320.3,4110.44 5320.15,4111.23 5299.27,4090.35 5300.11,4090.34 5300.96,4090.41 5301.82,4090.55 5302.7,4090.75 5303.58,4091.01 5305.36,4091.68 5307.16,4092.52 5313.44,4095.96 5316.04,4097.31 5317.72,4098.04 5318.54,4098.34 5319.35,4098.58 5320.14,4098.76 5320.9,4098.87 5321.65,4098.91 5322.38,4098.88 5323.09,4098.75 5323.77,4098.53 5324.43,4098.22 5325.06,4097.8
  region net KEY_GPIO: 5273.7,4015 5273.7,4005 5275.01,4004.94 5275.62,4004.88 5276.19,4004.78 5276.73,4004.66 5277.24,4004.52 5277.73,4004.35 5278.19,4004.16 5278.63,4003.95 5279.05,4003.72 5279.46,4003.47 5280.22,4002.91 5280.94,4002.28 5281.62,4001.6 5283.67,3999.25 5285.6,3997.06 5286.98,3995.69 5287.48,3995.24 5287.48,4024.76 5286.04,4023.39 5284.4,4021.61 5281.96,4018.77 5281.28,4018.05 5280.58,4017.39 5279.85,4016.8 5279.46,4016.53 5279.05,4016.28 5278.63,4016.05 5278.19,4015.84 5277.73,4015.65 5277.24,4015.48 5276.73,4015.34 5276.19,4015.22 5275.62,4015.12 5274.38,4015.01
  region net IIC_SCL: 5275,3965 5275,3955 5276.3,3954.94 5276.88,3954.88 5277.43,3954.78 5277.94,3954.66 5278.42,3954.52 5278.87,3954.35 5279.29,3954.16 5279.68,3953.95 5280.05,3953.72 5280.4,3953.47 5280.73,3953.2 5281.35,3952.61 5281.93,3951.95 5282.77,3950.86 5284.56,3948.39 5285.66,3947.06 5286.51,3946.15 5287.48,3945.24 5287.48,3974.76 5286.51,3973.85 5285.66,3972.94 5284.56,3971.61 5282.49,3968.77 5281.93,3968.05 5281.35,3967.39 5280.73,3966.8 5280.4,3966.53 5280.05,3966.28 5279.68,3966.05 5279.29,3965.84 5278.87,3965.65 5278.42,3965.48 5277.94,3965.34 5277.43,3965.22 5276.88,3965.12 5276.3,3965.06
  region net IIC_SDA: 5273.7,3915 5273.7,3905 5275.01,3904.94 5275.62,3904.88 5276.19,3904.78 5276.73,3904.66 5277.24,3904.52 5277.73,3904.35 5278.19,3904.16 5278.63,3903.95 5279.05,3903.72 5279.46,3903.47 5280.22,3902.91 5280.94,3902.28 5281.62,3901.6 5283.67,3899.25 5285.6,3897.06 5286.98,3895.69 5287.48,3895.24 5287.48,3924.76 5286.04,3923.39 5284.4,3921.61 5281.96,3918.77 5281.28,3918.05 5280.58,3917.39 5279.85,3916.8 5279.46,3916.53 5279.05,3916.28 5278.63,3916.05 5278.19,3915.84 5277.73,3915.65 5277.24,3915.48 5276.73,3915.34 5276.19,3915.22 5275.62,3915.12 5274.38,3915.01
  region net +3.3V: 4920.56,4068.43 4920.56,4052.68 4921.84,4052.73 4924.08,4052.94 4925.1,4053 4925.59,4052.99 4926.07,4052.94 4926.55,4052.86 4927.03,4052.72 4927.51,4052.53 4927.99,4052.27 4928.47,4051.95 4928.97,4051.55 4928.97,4069.56 4928.47,4069.16 4927.99,4068.84 4927.51,4068.58 4927.03,4068.39 4926.55,4068.26 4926.07,4068.17 4925.59,4068.12 4925.1,4068.11 4924.08,4068.17 4921.84,4068.38
  region net +3.3V: 3731.1,3570.16 3731.1,3589.84 ccw(c3731.1,3688.27) 3790.16,3609.53 3790.16,3550.47 ccw(c3731.1,3471.73)
  region net +5V: 4510.12,3397.87 4510.12,3382.13 ccw(c4510.12,3303.39) 4462.87,3366.38 4462.87,3413.62 ccw(c4510.12,3476.61)
  region net +3.3V: 4209.29,4099.54 4193.54,4099.54 4193.45,4097.3 4193.2,4094.91 4192.78,4092.41 4192.21,4089.85 4191.49,4087.28 4190.64,4084.74 4189.66,4082.28 4188.56,4079.95 4187.77,4078.5 4186.93,4077.13 4186.04,4075.88 4185.12,4074.74 4238.27,4074.74 4237.55,4075.5 4236.75,4076.25 4235.42,4077.35 4233.43,4078.79 4230.11,4080.89 4220.47,4086.47 4217.62,4088.3 4215.52,4089.81 4214.09,4090.99 4213.21,4091.79 4212.4,4092.62 4211.68,4093.46 4211.03,4094.33 4210.48,4095.21 4210.02,4096.13 4209.83,4096.6 4209.67,4097.07 4209.54,4097.55 4209.43,4098.04 4209.35,4098.53 4209.31,4099.03
  region net +3.3V: 4193.54,4003.06 4209.29,4003.06 4209.31,4003.57 4209.35,4004.07 4209.43,4004.57 4209.54,4005.06 4209.67,4005.54 4209.83,4006.01 4210.02,4006.48 4210.48,4007.39 4211.03,4008.28 4211.68,4009.14 4212.4,4009.99 4213.21,4010.81 4214.55,4012.01 4216.03,4013.18 4218.17,4014.68 4222.26,4017.2 4231.25,4022.41 4233.95,4024.17 4235.42,4025.25 4236.75,4026.35 4237.55,4027.1 4238.27,4027.87 4185.12,4027.87 4186.04,4026.73 4186.93,4025.47 4187.77,4024.11 4188.94,4021.89 4190,4019.51 4190.94,4017.03 4191.74,4014.47 4192.41,4011.9 4192.93,4009.35 4193.3,4006.88 4193.5,4004.53
Bottom Layer:
  region net +3.3V: 5273.7,3817.87 5273.7,3802.13 5274.67,3802.09 5275.63,3801.97 5276.57,3801.79 5277.5,3801.53 5278.42,3801.22 5279.32,3800.85 5281.08,3799.97 5282.78,3798.93 5284.41,3797.77 5286.74,3795.88 5287.48,3795.24 5287.48,3824.76 5285.21,3822.85 5283.6,3821.64 5281.94,3820.53 5280.21,3819.56 5279.32,3819.15 5278.42,3818.78 5277.5,3818.47 5276.57,3818.21 5275.63,3818.03 5274.67,3817.91
  region net +3.3V: 5284.15,3817.87 5284.15,3802.13 5285.43,3802.17 5287.67,3802.39 5288.69,3802.44 5289.18,3802.43 5289.67,3802.39 5290.14,3802.3 5290.62,3802.16 5291.1,3801.97 5291.58,3801.72 5292.06,3801.39 5292.56,3800.99 5292.56,3819.01 5292.06,3818.61 5291.58,3818.28 5291.1,3818.03 5290.62,3817.84 5290.14,3817.7 5289.67,3817.61 5289.18,3817.57 5288.69,3817.56 5287.67,3817.61 5285.43,3817.83
  region net +3.3V: 5047.87,3596.07 5032.13,3596.07 5032.09,3595.28 5031.99,3594.57 5031.83,3593.92 5031.62,3593.34 5031.35,3592.82 5031.03,3592.33 5030.68,3591.88 5030.28,3591.45 5029.38,3590.62 5027.32,3588.81 5026.21,3587.67 5044.22,3587.67 5043.92,3588.11 5043.79,3588.57 5043.79,3589.05 5043.92,3589.53 5044.15,3590.03 5044.47,3590.53 5045.27,3591.58 5046.61,3593.21 5047.01,3593.77 5047.36,3594.33 5047.63,3594.91 5047.81,3595.49
  region net +3.3V: 4929.04,4044.21 4944.78,4044.21 4944.74,4045.48 4944.52,4047.73 4944.47,4048.74 4944.48,4049.24 4944.52,4049.72 4944.61,4050.2 4944.75,4050.67 4944.94,4051.15 4945.19,4051.63 4945.51,4052.12 4945.92,4052.61 4927.9,4052.61 4928.3,4052.12 4928.63,4051.63 4928.88,4051.15 4929.07,4050.67 4929.21,4050.2 4929.3,4049.72 4929.34,4049.24 4929.35,4048.74 4929.3,4047.73 4929.08,4045.48
  region net +3.3V: 5048.86,3787.73 5050.33,3789.08 5052.01,3790.41 5053.87,3791.73 5056.97,3793.64 5060.34,3795.45 5063.91,3797.11 5067.58,3798.6 5071.28,3799.87 5074.91,3800.89 5078.39,3801.63 5080.58,3801.94 5082.65,3802.11 5083.62,3802.13 5033.12,3802.13 5033.66,3802.11 5034.76,3802 5035.31,3801.9 5035.84,3801.77 5036.34,3801.62 5036.81,3801.44 5037.23,3801.24 5037.59,3801.02 5037.89,3800.77 5038.11,3800.51 5038.25,3800.22 5038.29,3799.91 5038.22,3799.58 5038.04,3799.23 5037.73,3798.86

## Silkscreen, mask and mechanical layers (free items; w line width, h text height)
Top Silkscreen Layer:
  text "GND DP DM LED KEY SCL SDA ADC 3.3V GND" at 5229.37,4225.73 h12.78 r270
Mechanical Layer:
  lines w1 net "": 4933.44,4208.74 ccw(c5012.18,4208.74) 5012.18,4130 5074.7,4130 ccw(c5074.7,4208.74) 5153.44,4208.74 5153.44,4421.26 ccw(c5074.7,4421.26) 5074.7,4500 5012.18,4500 ccw(c5012.18,4421.26) 4933.44,4421.26 4933.44,4208.74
